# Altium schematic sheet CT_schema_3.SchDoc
size 504 x 432 mm
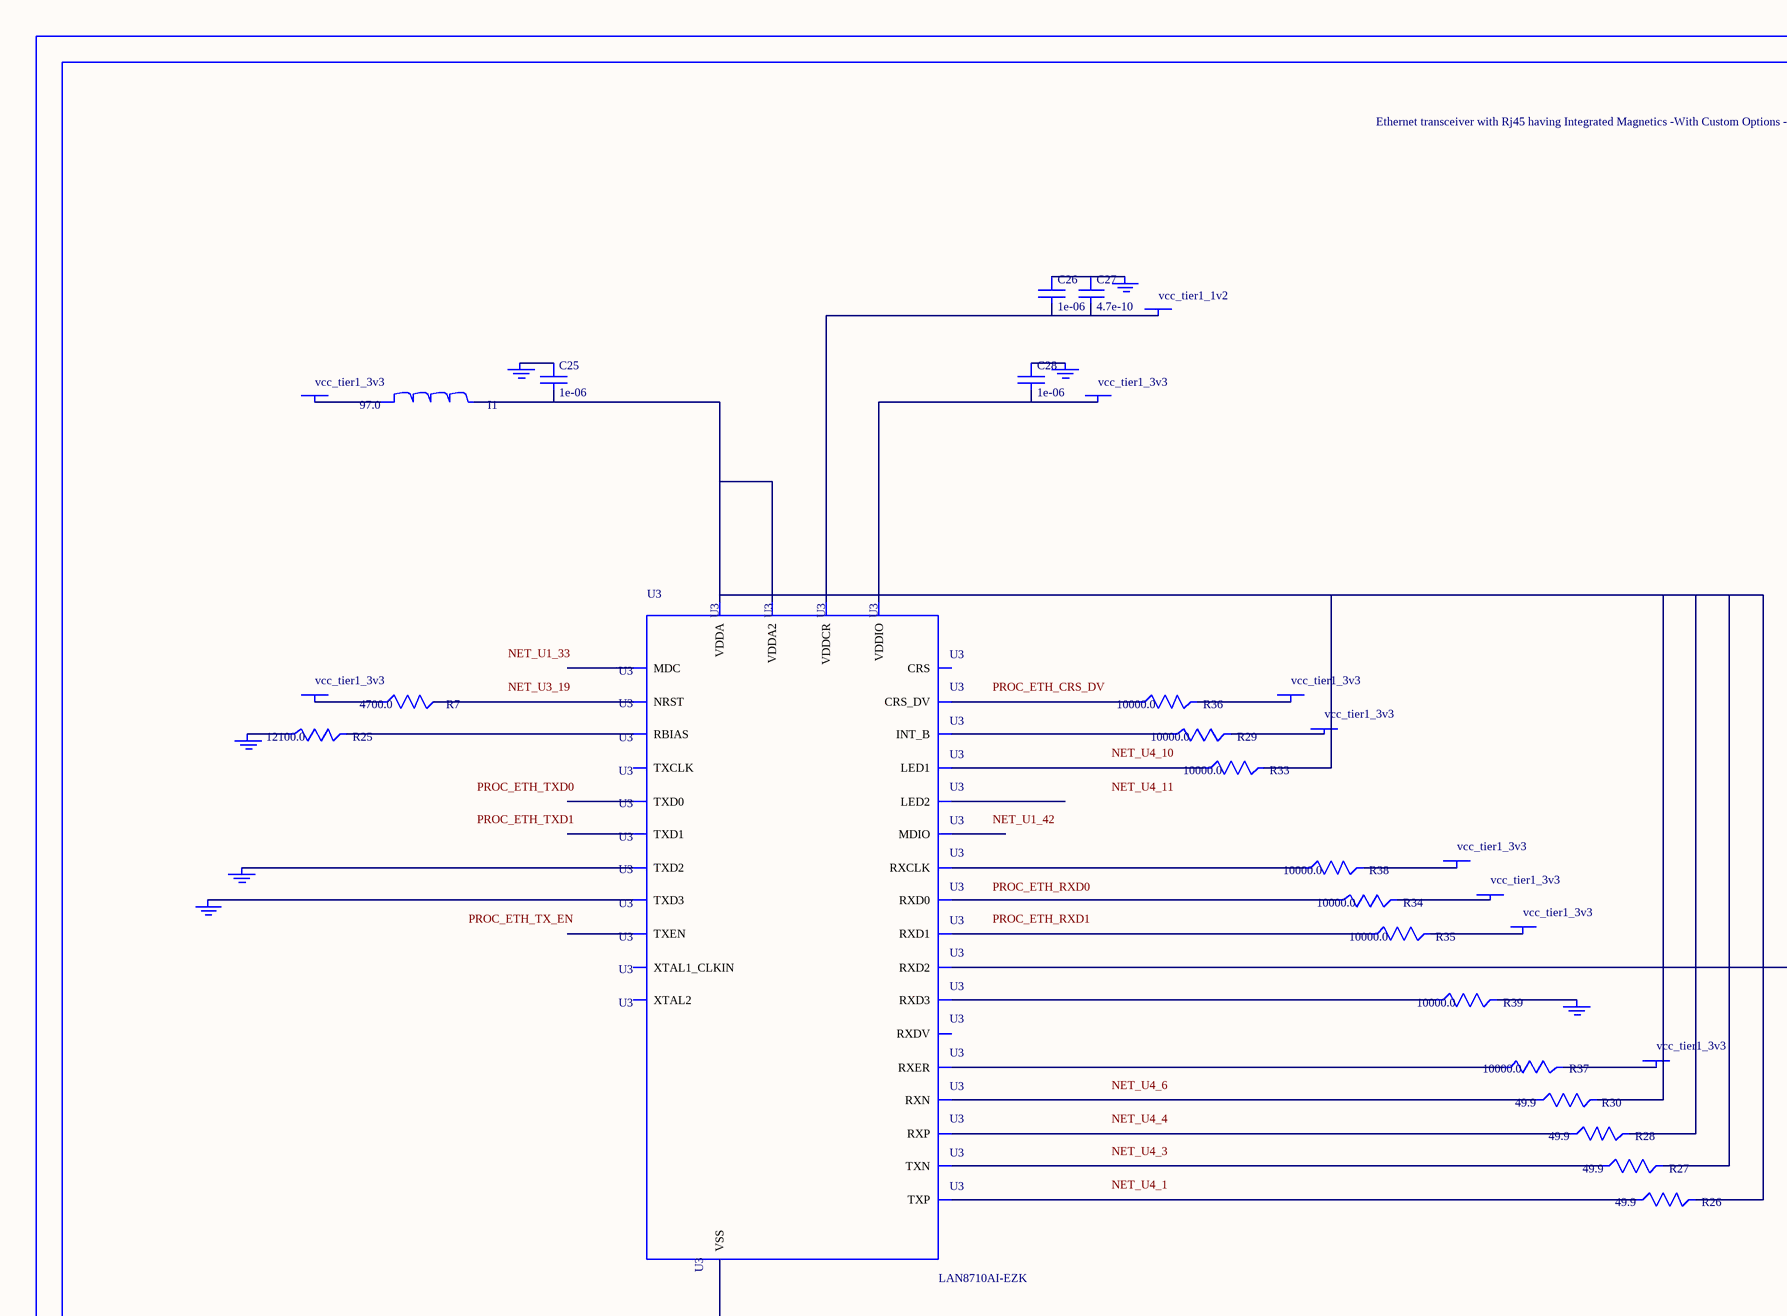
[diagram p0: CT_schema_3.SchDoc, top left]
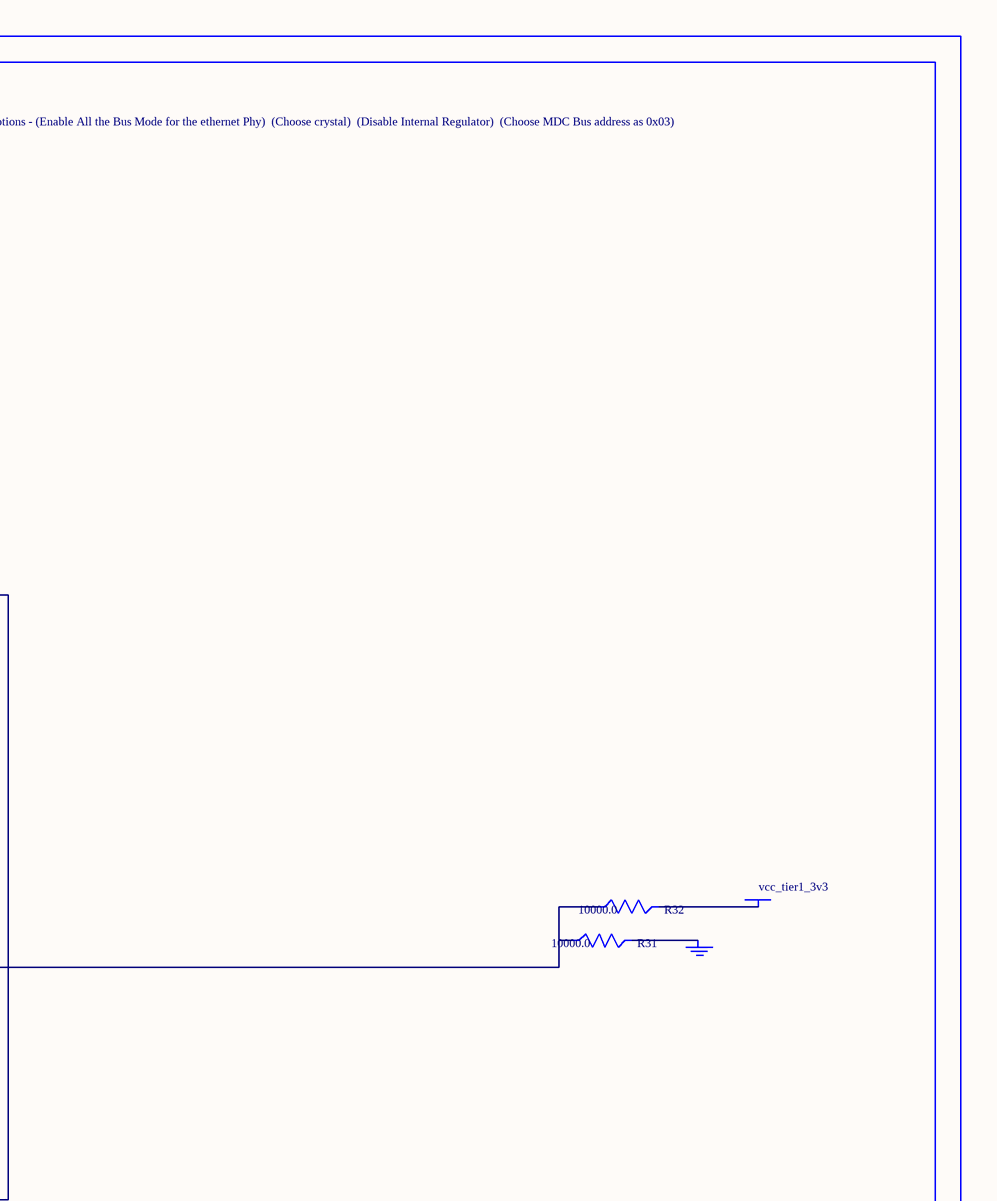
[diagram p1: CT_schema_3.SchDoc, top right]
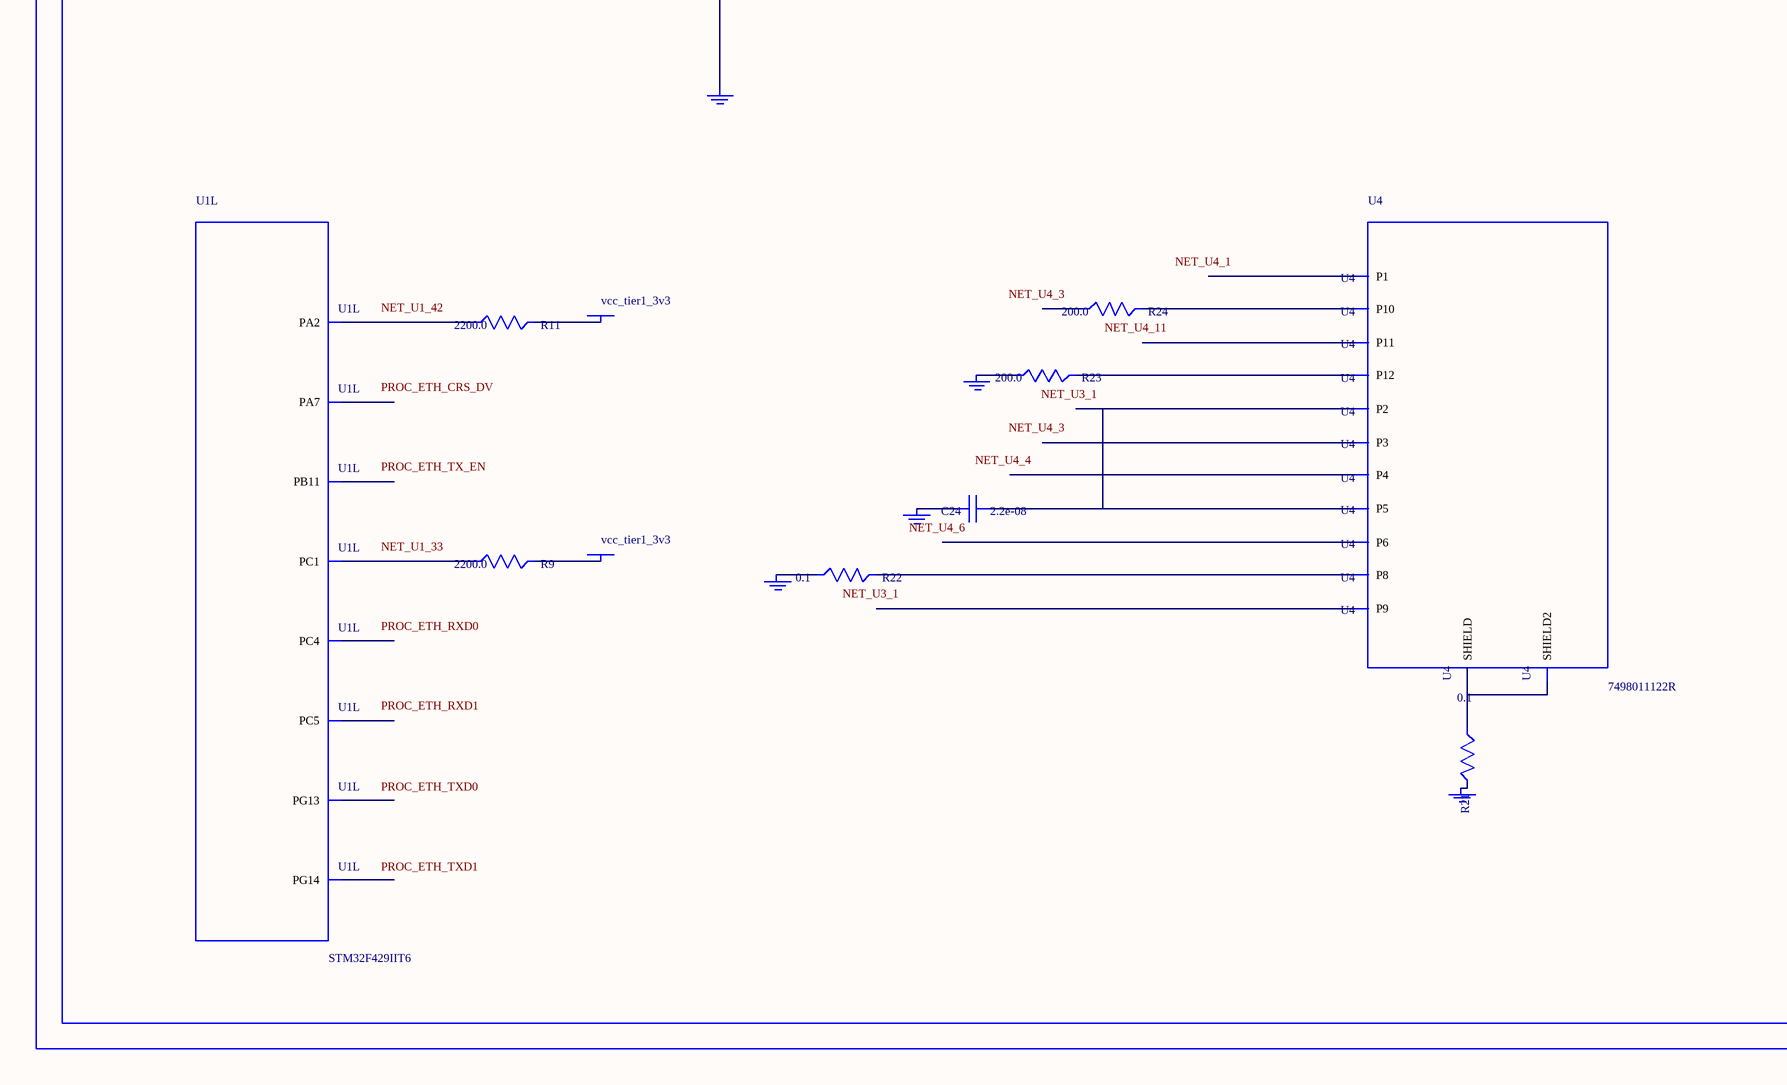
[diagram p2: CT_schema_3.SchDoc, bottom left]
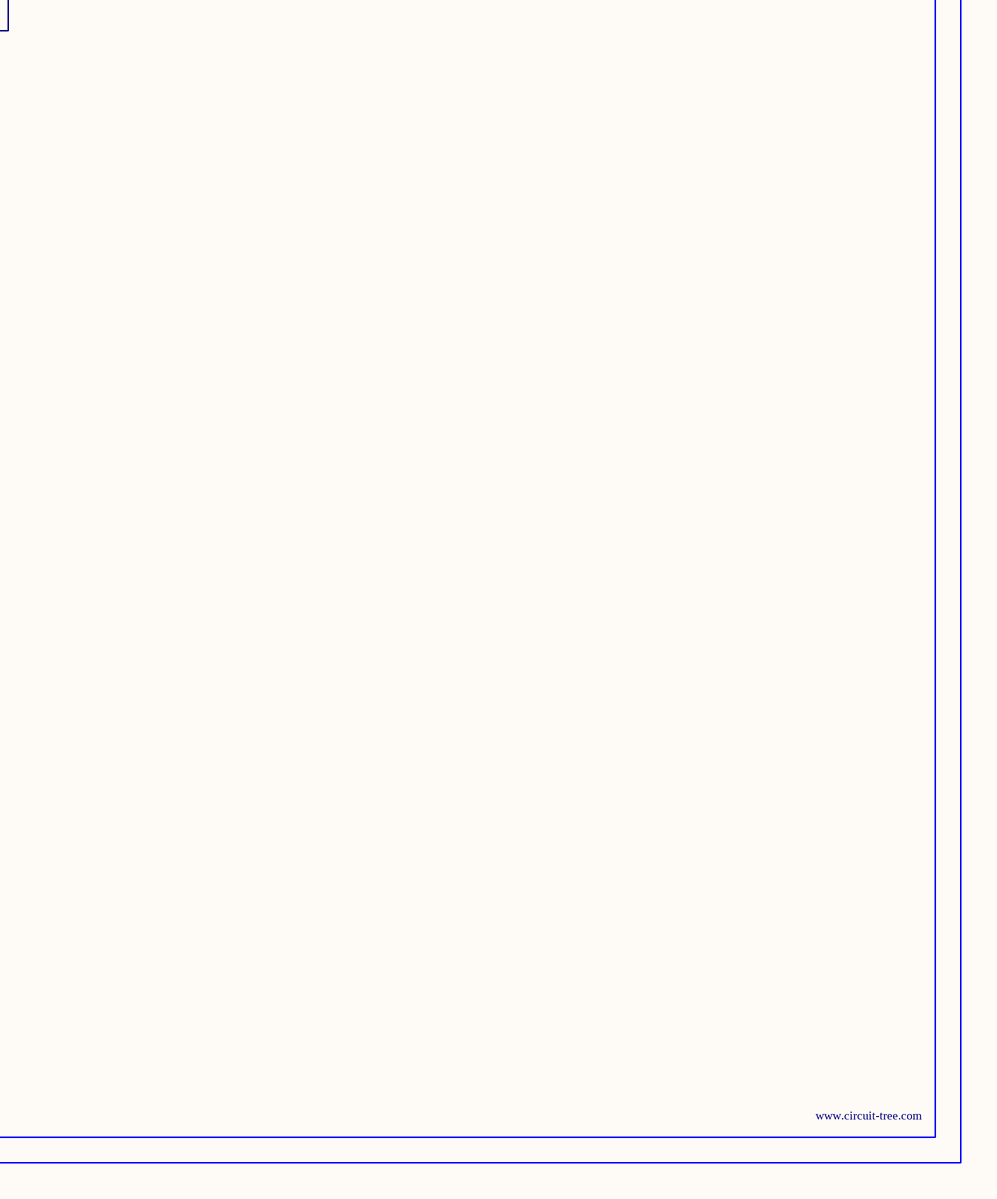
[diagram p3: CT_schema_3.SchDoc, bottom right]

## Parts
BORDER2  (no value)
C24  2.2e-08  [C0402]
C25  1e-06  [C0603]
C26  1e-06  [C0603]
C27  4.7e-10  [C0603]
C28  1e-06  [C0603]
GND_INSTANCE_2_0  (no value)
GND_INSTANCE_2_1  (no value)
GND_INSTANCE_2_2  (no value)
GND_INSTANCE_2_3  (no value)
GND_INSTANCE_2_4  (no value)
GND_INSTANCE_2_5  (no value)
GND_INSTANCE_2_6  (no value)
GND_INSTANCE_2_7  (no value)
GND_INSTANCE_2_8  (no value)
GND_INSTANCE_2_9  (no value)
GND_INSTANCE_2_10  (no value)
GND_INSTANCE_2_11  (no value)
GND_INSTANCE_2_12  (no value)
I1  97.0  [R0603]
POWER_INSTANCE_2_0  vcc_tier1_3v3
POWER_INSTANCE_2_1  vcc_tier1_1v2
POWER_INSTANCE_2_2  vcc_tier1_3v3
POWER_INSTANCE_2_3  vcc_tier1_3v3
POWER_INSTANCE_2_4  vcc_tier1_3v3
POWER_INSTANCE_2_5  vcc_tier1_3v3
POWER_INSTANCE_2_6  vcc_tier1_3v3
POWER_INSTANCE_2_7  vcc_tier1_3v3
POWER_INSTANCE_2_8  vcc_tier1_3v3
POWER_INSTANCE_2_9  vcc_tier1_3v3
POWER_INSTANCE_2_10  vcc_tier1_3v3
POWER_INSTANCE_2_11  vcc_tier1_3v3
POWER_INSTANCE_2_12  vcc_tier1_3v3
R7  4700.0  [R0603]
R9  2200.0  [R0603]
R11  2200.0  [R0603]
R21  0.1  [R0603]
R22  0.1  [R0603]
R23  200.0  [R0603]
R24  200.0  [R0603]
R25  12100.0  [R0603]
R26  49.9  [R0603]
R27  49.9  [R0603]
R28  49.9  [R0603]
R29  10000.0  [R0603]
R30  49.9  [R0603]
R31  10000.0  [R0603]
R32  10000.0  [R0603]
R33  10000.0  [R0603]
R34  10000.0  [R0603]
R35  10000.0  [R0603]
R36  10000.0  [R0603]
R37  10000.0  [R0603]
R38  10000.0  [R0603]
R39  10000.0  [R0603]
U1  STM32F429IIT6  [LQFP176]  (part L of 15)
U3  LAN8710AI-EZK  [QFN-32]
U4  7498011122R  [7498011122R]

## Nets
NetC24_1: C24.1 U4.2(P2) U4.5(P5)
NetC24_2: C24.2 GND_INSTANCE_2_9.0(GND)
NetC25_1: C25.1 GND_INSTANCE_2_0.0(GND)
NetC25_2: C25.2 I1.2 R26.2 R27.2 R28.2 R30.2 R33.2 U3.1(VDDA) U3.27(VDDA2)
NetC26_1: C26.1 C27.1 GND_INSTANCE_2_1.0(GND)
NetC26_2: C26.2 C27.2 POWER_INSTANCE_2_1.0(PWR) U3.6(VDDCR)
NetC28_1: C28.1 GND_INSTANCE_2_4.0(GND)
NetC28_2: C28.2 POWER_INSTANCE_2_6.0(PWR) U3.12(VDDIO)
NetGND_INSTANCE_2_2_0: GND_INSTANCE_2_2.0(GND) R39.2
NetGND_INSTANCE_2_3_0: GND_INSTANCE_2_3.0(GND) R31.2
NetGND_INSTANCE_2_5_0: GND_INSTANCE_2_5.0(GND) U3.24(TXD2)
NetGND_INSTANCE_2_6_0: GND_INSTANCE_2_6.0(GND) U3.25(TXD3)
NetGND_INSTANCE_2_7_0: GND_INSTANCE_2_7.0(GND) R25.1
NetGND_INSTANCE_2_8_0: GND_INSTANCE_2_8.0(GND) U3.EXP(VSS)
NetGND_INSTANCE_2_10_0: GND_INSTANCE_2_10.0(GND) R22.1
NetGND_INSTANCE_2_11_0: GND_INSTANCE_2_11.0(GND) R23.1
NetGND_INSTANCE_2_12_0: GND_INSTANCE_2_12.0(GND) R21.2
NetI1_1: I1.1 POWER_INSTANCE_2_0.0(PWR)
NetPOWER_INSTANCE_2_2_0: POWER_INSTANCE_2_2.0(PWR) R38.2
NetPOWER_INSTANCE_2_3_0: POWER_INSTANCE_2_3.0(PWR) R32.2
NetPOWER_INSTANCE_2_4_0: POWER_INSTANCE_2_4.0(PWR) R35.2
NetPOWER_INSTANCE_2_5_0: POWER_INSTANCE_2_5.0(PWR) R34.2
NetPOWER_INSTANCE_2_7_0: POWER_INSTANCE_2_7.0(PWR) R37.2
NetPOWER_INSTANCE_2_8_0: POWER_INSTANCE_2_8.0(PWR) R36.2
NetPOWER_INSTANCE_2_9_0: POWER_INSTANCE_2_9.0(PWR) R29.2
NetPOWER_INSTANCE_2_10_0: POWER_INSTANCE_2_10.0(PWR) R7.1
NetPOWER_INSTANCE_2_11_0: POWER_INSTANCE_2_11.0(PWR) R9.2
NetPOWER_INSTANCE_2_12_0: POWER_INSTANCE_2_12.0(PWR) R11.2
NetR7_2: R7.2 U3.19(NRST)
NetR9_1: R9.1 U1.33(PC1)
NetR11_1: R11.1 U1.42(PA2)
NetR21_1: R21.1 U4.13(SHIELD) U4.14(SHIELD2)
NetR22_2: R22.2 U4.8(P8)
NetR23_2: R23.2 U4.12(P12)
NetR24_2: R24.2 U4.10(P10)
NetR25_2: R25.2 U3.32(RBIAS)
NetR26_1: R26.1 U3.29(TXP)
NetR27_1: R27.1 U3.28(TXN)
NetR28_1: R28.1 U3.31(RXP)
NetR29_1: R29.1 U3.18(INT_B)
NetR30_1: R30.1 U3.30(RXN)
NetR31_1: R31.1 R32.1 U3.9(RXD2)
NetR33_1: R33.1 U3.3(LED1)
NetR34_1: R34.1 U3.11(RXD0)
NetR35_1: R35.1 U3.10(RXD1)
NetR36_1: R36.1 U3.15(CRS_DV)
NetR37_1: R37.1 U3.13(RXER)
NetR38_1: R38.1 U3.7(RXCLK)
NetR39_1: R39.1 U3.8(RXD3)

Not connected (* = marked no-connect by the designer): R24 1; U1 53(PA7) 54(PC4) 55(PC5) 80(PB11) 156(PG13) 157(PG14); U3 2(LED2) 4(XTAL2) 5(XTAL1_CLKIN) 14(CRS) 16(MDIO) 17(MDC) 20(TXCLK) 21(TXEN) 22(TXD0) 23(TXD1) 26(RXDV); U4 1(P1) 3(P3) 4(P4) 6(P6) 9(P9) 11(P11)

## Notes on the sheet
- Labels drawn without touching a wire or pin: NET_U1_33, NET_U1_42, NET_U3_1, NET_U3_19, NET_U4_1, NET_U4_3, NET_U4_4, NET_U4_6, NET_U4_10, NET_U4_11, PROC_ETH_CRS_DV, PROC_ETH_RXD0, PROC_ETH_RXD1, PROC_ETH_TX_EN, PROC_ETH_TXD0, PROC_ETH_TXD1

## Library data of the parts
BORDER2 = BORDER_PAGE2
C24 = C0402C223K3RAC
C25 C26 C28 = C0603C105K3RACTU
C27 = 06031C471KAZ2A
GND_INSTANCE_2_0-GND_INSTANCE_2_12 = GND
I1 = I1
POWER_INSTANCE_2_0-POWER_INSTANCE_2_12 = PWR
R7 = RC0603JR-074K7L
R9 R11 = RC0603JR-072K2L
R21 R22 = ERJ-3RSFR10V
R23 R24 = RC0603JR-07200RL
R25 = TNPW060312K1BEEA
R26-R28 R30 = RC0603FR-0749R9L
R29 R31-R39 = RC0603JR-0710KL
